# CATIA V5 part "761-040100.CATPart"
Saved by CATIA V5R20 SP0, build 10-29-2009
Part number: 761-040100
Source: Unknown
Property "ARTICLENO": "761-040100"
Property "BOMINFO": "761-040100"
Property "CODE": "761-040100"
Property "H": "40.000"
Property "L1": "100.000"
Property "L2": "80.000"
Property "LINA": "761-040100"
Property "NB": "761-040100"
Property "NBSYN": "$CODE."
Property "NN": "761"
Property "NT": "VW/AUDI Keys"
Property "P": "4.000"
Property "SUPPLIER": "CF"
Bounding box of the stored display mesh (mm): x -50 to 50, y 0 to 40, z -11 to 11
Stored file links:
  C:\Users\Utente\Desktop\3D files 761\761-040100.CATPart
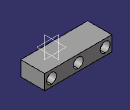
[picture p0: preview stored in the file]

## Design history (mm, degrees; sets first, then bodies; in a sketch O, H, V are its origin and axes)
Body1 "Geometry.1" (main body)
  Solid1 "761-040100.catpart": solid without history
